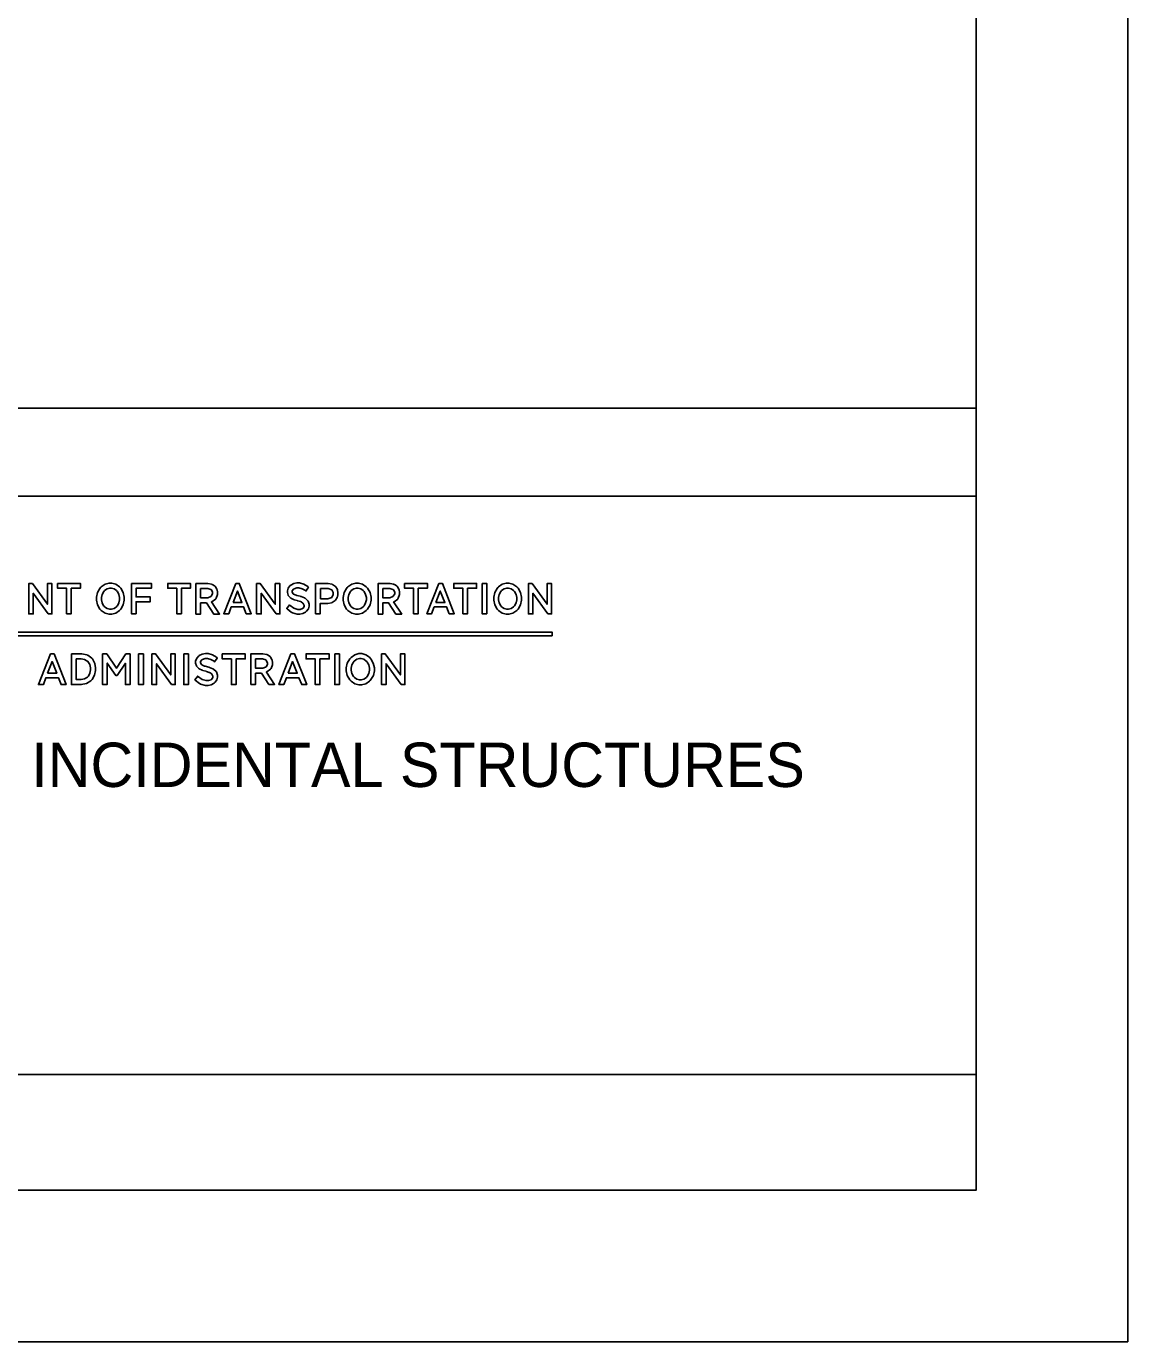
# Model space of a CAD drawing. Extents: x -0.5 to 19.9, y 5.2 to 17.3.
# Drawn here: x 17.634 to 19.938, y 5.667 to 8.417 of the extents above; entities that cross this region are included whole.
import ezdxf

# ---------------------------------------------------------------- set-up
doc = ezdxf.new("R2010")
doc.units = 0
for name, color, linetype in [('BORD-LINE', 7, 'Continuous'), ('MSHA-LOGO', 7, 'Continuous'), ('TTLB-TEXT', 7, 'Continuous'), ('USER-CLIP', 7, 'Continuous')]:
    doc.layers.add(name, color=color, linetype=linetype)

msp = doc.modelspace()

# ---------------------------------------------------------------- linework, layer by layer
at = {"layer": 'BORD-LINE'}
for p, q in [((19.6208, 7.6193), (12.2466, 7.6193)), ((19.6208, 7.4352), (15.1479, 7.4352)), ((15.1479, 6.2262), (19.6208, 6.2262))]:
    msp.add_line(p, q, dxfattribs=at)
msp.add_lwpolyline([(12.2466, 16.3375), (19.6208, 16.3375), (19.6208, 5.9844), (12.2466, 5.9844)], close=True, dxfattribs=at)
at = {"layer": 'MSHA-LOGO'}
for points in [[(17.6799, 7.189), (17.6485, 7.2324), (17.6485, 7.189), (17.639, 7.189), (17.639, 7.2525), (17.6465, 7.2525), (17.6779, 7.2091), (17.6779, 7.2525), (17.6874, 7.2525), (17.6874, 7.189)], [(17.6989, 7.2528), (17.747, 7.2528), (17.747, 7.2426), (17.728, 7.2426), (17.728, 7.1893), (17.7182, 7.1893), (17.7182, 7.2426), (17.6992, 7.2426), (17.6992, 7.2528)], [(17.7892, 7.2439), (17.7905, 7.2455), (17.7985, 7.251), (17.8069, 7.2535), (17.8098, 7.2535), (17.8126, 7.2535), (17.821, 7.2512), (17.829, 7.2458), (17.8304, 7.2443), (17.8318, 7.2427), (17.8367, 7.2338), (17.8389, 7.2241), (17.8389, 7.2209), (17.8389, 7.2177), (17.8367, 7.2081), (17.8318, 7.1991), (17.8304, 7.1975), (17.829, 7.196), (17.821, 7.1906), (17.8126, 7.1883), (17.8098, 7.1883), (17.8069, 7.1883), (17.7985, 7.1906), (17.7905, 7.196), (17.7892, 7.1975), (17.7878, 7.1991), (17.7828, 7.208), (17.7807, 7.2177), (17.7807, 7.2209), (17.7807, 7.2241), (17.7828, 7.2335), (17.7878, 7.2424)], [(17.7967, 7.2051), (17.7976, 7.204), (17.8028, 7.2004), (17.8083, 7.1989), (17.8101, 7.1989), (17.8119, 7.1989), (17.8174, 7.2004), (17.8226, 7.204), (17.8235, 7.2051), (17.8244, 7.2061), (17.8276, 7.212), (17.8291, 7.2187), (17.8291, 7.2209), (17.8291, 7.2231), (17.8276, 7.2298), (17.8244, 7.2357), (17.8235, 7.2367), (17.8226, 7.2378), (17.8174, 7.2414), (17.8119, 7.2429), (17.8101, 7.2429), (17.8083, 7.2429), (17.8028, 7.2414), (17.7976, 7.2378), (17.7967, 7.2367), (17.7958, 7.2357), (17.7925, 7.2298), (17.7911, 7.2231), (17.7911, 7.2209), (17.7911, 7.2187), (17.7924, 7.212), (17.7957, 7.2061)], [(17.8536, 7.2528), (17.8955, 7.2528), (17.8955, 7.2426), (17.8634, 7.2426), (17.8634, 7.2245), (17.8932, 7.2245), (17.8932, 7.2143), (17.8634, 7.2143), (17.8634, 7.1893), (17.8536, 7.1893)], [(17.9292, 7.2528), (17.9773, 7.2528), (17.9773, 7.2426), (17.9583, 7.2426), (17.9583, 7.1893), (17.9485, 7.1893), (17.9485, 7.2426), (17.9296, 7.2426), (17.9296, 7.2528)], [(17.9888, 7.189), (17.9888, 7.2525), (18.011, 7.2525), (18.0138, 7.2525), (18.0213, 7.2511), (18.0222, 7.2508), (18.0229, 7.2506), (18.0286, 7.2467), (18.029, 7.2462), (18.0294, 7.2458), (18.0324, 7.2406), (18.0326, 7.24), (18.0329, 7.2394), (18.0336, 7.2342), (18.0336, 7.2324), (18.0336, 7.2295), (18.0309, 7.2217), (18.0303, 7.2209), (18.0298, 7.2201), (18.0222, 7.2143), (18.0212, 7.214), (18.0382, 7.1887), (18.0261, 7.1887), (18.0107, 7.212), (17.9986, 7.212), (17.9986, 7.1887), (17.9888, 7.1887)], [(17.9986, 7.2423), (17.9986, 7.2229), (18.0114, 7.2229), (18.0136, 7.2229), (18.0196, 7.2251), (18.0202, 7.2255), (18.0207, 7.2259), (18.0235, 7.2313), (18.0235, 7.2331), (18.0235, 7.2348), (18.021, 7.2396), (18.0205, 7.24), (18.02, 7.2404), (18.0133, 7.2423), (18.011, 7.2423)], [(18.0719, 7.2528), (18.0794, 7.2528), (18.1043, 7.1893), (18.0938, 7.1893), (18.0883, 7.2035), (18.0627, 7.2035), (18.0572, 7.1893), (18.047, 7.1893)], [(18.0663, 7.2127), (18.085, 7.2127), (18.0755, 7.2367)], [(18.1566, 7.189), (18.1252, 7.2324), (18.1252, 7.189), (18.1157, 7.189), (18.1157, 7.2525), (18.1233, 7.2525), (18.1547, 7.2091), (18.1547, 7.2525), (18.1642, 7.2525), (18.1642, 7.189)], [(18.213, 7.2114), (18.2126, 7.2117), (18.2085, 7.2144), (18.208, 7.2147), (18.2075, 7.2148), (18.2018, 7.2165), (18.2012, 7.2166), (18.2005, 7.2168), (18.1943, 7.2187), (18.1936, 7.2189), (18.193, 7.2192), (18.1872, 7.2219), (18.1868, 7.2222), (18.1863, 7.2226), (18.1822, 7.2269), (18.1819, 7.2275), (18.1815, 7.2281), (18.1799, 7.2338), (18.1799, 7.2357), (18.1799, 7.2374), (18.1814, 7.2426), (18.185, 7.2476), (18.1861, 7.2485), (18.1872, 7.2494), (18.1933, 7.2525), (18.1999, 7.2538), (18.2021, 7.2538), (18.2053, 7.2538), (18.2147, 7.2515), (18.2228, 7.2462), (18.2241, 7.2446), (18.2188, 7.2367), (18.2176, 7.2378), (18.2109, 7.2416), (18.2041, 7.2433), (18.2018, 7.2433), (18.1997, 7.2433), (18.1939, 7.2416), (18.1933, 7.2413), (18.1927, 7.241), (18.19, 7.237), (18.19, 7.2357), (18.19, 7.2345), (18.1922, 7.2311), (18.1926, 7.2308), (18.1931, 7.2305), (18.1985, 7.228), (18.1992, 7.2278), (18.1998, 7.2277), (18.207, 7.2258), (18.2077, 7.2255), (18.2085, 7.2253), (18.2156, 7.2226), (18.2162, 7.2222), (18.2169, 7.2219), (18.2224, 7.2173), (18.2228, 7.2166), (18.2232, 7.216), (18.2254, 7.2095), (18.2254, 7.2074), (18.2254, 7.2055), (18.2239, 7.1999), (18.2202, 7.1948), (18.2192, 7.1939), (18.2181, 7.193), (18.2121, 7.1899), (18.2058, 7.1887), (18.2038, 7.1887), (18.2002, 7.1887), (18.1905, 7.1914), (18.1894, 7.192), (18.1882, 7.1925), (18.1792, 7.1994), (18.1786, 7.2002), (18.1845, 7.2077), (18.1858, 7.2063), (18.1934, 7.2009), (18.2017, 7.1985), (18.2044, 7.1985), (18.2064, 7.1985), (18.2119, 7.2002), (18.2123, 7.2005), (18.2128, 7.2008), (18.2152, 7.2048), (18.2152, 7.2061), (18.2151, 7.2067), (18.2133, 7.211)], [(18.2391, 7.189), (18.2391, 7.2525), (18.262, 7.2525), (18.265, 7.2525), (18.273, 7.2511), (18.2738, 7.2508), (18.2746, 7.2505), (18.2806, 7.2464), (18.281, 7.2459), (18.2814, 7.2454), (18.2845, 7.2399), (18.2846, 7.2393), (18.2848, 7.2388), (18.2856, 7.2335), (18.2856, 7.2318), (18.2856, 7.2299), (18.2845, 7.2248), (18.2843, 7.2242), (18.284, 7.2236), (18.2808, 7.2181), (18.2804, 7.2176), (18.2799, 7.2171), (18.2736, 7.213), (18.2728, 7.2127), (18.272, 7.2124), (18.2643, 7.211), (18.2617, 7.211), (18.2486, 7.211), (18.2486, 7.1893), (18.2391, 7.1893)], [(18.2493, 7.2423), (18.2493, 7.2209), (18.2624, 7.2209), (18.2649, 7.2209), (18.2727, 7.2236), (18.2761, 7.2297), (18.2761, 7.2318), (18.2761, 7.2337), (18.2729, 7.2396), (18.2655, 7.2423), (18.263, 7.2423)], [(18.3052, 7.2439), (18.3066, 7.2455), (18.3146, 7.251), (18.323, 7.2535), (18.3259, 7.2535), (18.3287, 7.2535), (18.3371, 7.2512), (18.3451, 7.2458), (18.3465, 7.2443), (18.3478, 7.2427), (18.3528, 7.2338), (18.355, 7.2241), (18.355, 7.2209), (18.355, 7.2177), (18.3528, 7.2081), (18.3478, 7.1991), (18.3465, 7.1975), (18.3451, 7.196), (18.3371, 7.1906), (18.3287, 7.1883), (18.3259, 7.1883), (18.323, 7.1883), (18.3146, 7.1906), (18.3066, 7.196), (18.3052, 7.1975), (18.3038, 7.1991), (18.2989, 7.208), (18.2967, 7.2177), (18.2967, 7.2209), (18.2968, 7.2232), (18.299, 7.2335), (18.3038, 7.2424)], [(18.3128, 7.2051), (18.3136, 7.204), (18.3188, 7.2004), (18.3243, 7.1989), (18.3262, 7.1989), (18.328, 7.1989), (18.3335, 7.2004), (18.3387, 7.204), (18.3396, 7.2051), (18.3405, 7.2061), (18.3437, 7.212), (18.3452, 7.2187), (18.3452, 7.2209), (18.3452, 7.2231), (18.3437, 7.2298), (18.3405, 7.2357), (18.3396, 7.2367), (18.3387, 7.2378), (18.3335, 7.2414), (18.328, 7.2429), (18.3262, 7.2429), (18.3244, 7.2429), (18.319, 7.2414), (18.3137, 7.2378), (18.3128, 7.2367), (18.3119, 7.2357), (18.3086, 7.2298), (18.3072, 7.2231), (18.3072, 7.2209), (18.3072, 7.2187), (18.3085, 7.212), (18.3118, 7.2061)], [(18.3697, 7.189), (18.3697, 7.2525), (18.3919, 7.2525), (18.3947, 7.2525), (18.4023, 7.2511), (18.4031, 7.2508), (18.4038, 7.2506), (18.4095, 7.2467), (18.4099, 7.2462), (18.4104, 7.2458), (18.4133, 7.2406), (18.4135, 7.24), (18.4137, 7.2394), (18.4145, 7.2342), (18.4145, 7.2324), (18.4145, 7.2295), (18.4118, 7.2217), (18.4113, 7.2209), (18.4107, 7.2201), (18.4031, 7.2143), (18.4021, 7.214), (18.4191, 7.1887), (18.407, 7.1887), (18.3916, 7.212), (18.3795, 7.212), (18.3795, 7.1887), (18.3697, 7.1887)], [(18.3795, 7.2423), (18.3795, 7.2229), (18.3923, 7.2229), (18.3945, 7.2229), (18.4005, 7.2251), (18.4011, 7.2255), (18.4016, 7.2259), (18.4044, 7.2313), (18.4044, 7.2331), (18.4044, 7.2348), (18.4019, 7.2396), (18.4014, 7.24), (18.4009, 7.2404), (18.3942, 7.2423), (18.3919, 7.2423)], [(18.4247, 7.2528), (18.4728, 7.2528), (18.4728, 7.2426), (18.4538, 7.2426), (18.4538, 7.1893), (18.444, 7.1893), (18.444, 7.2426), (18.425, 7.2426), (18.425, 7.2528)], [(18.4967, 7.2528), (18.5042, 7.2528), (18.5291, 7.1893), (18.5186, 7.1893), (18.513, 7.2035), (18.4872, 7.2035), (18.4816, 7.1893), (18.4718, 7.1893)], [(18.4908, 7.2127), (18.5094, 7.2127), (18.4999, 7.2367)], [(18.5278, 7.2528), (18.5759, 7.2528), (18.5759, 7.2426), (18.5569, 7.2426), (18.5569, 7.1893), (18.5471, 7.1893), (18.5471, 7.2426), (18.5281, 7.2426), (18.5281, 7.2528)], [(18.5873, 7.2528), (18.5971, 7.2528), (18.5971, 7.1893), (18.5873, 7.1893)], [(18.6201, 7.2439), (18.6214, 7.2455), (18.6294, 7.251), (18.6378, 7.2535), (18.6407, 7.2535), (18.6435, 7.2535), (18.6519, 7.2512), (18.6599, 7.2458), (18.6613, 7.2443), (18.6627, 7.2427), (18.6676, 7.2338), (18.6698, 7.2241), (18.6698, 7.2209), (18.6698, 7.2177), (18.6676, 7.2081), (18.6627, 7.1991), (18.6613, 7.1975), (18.6599, 7.196), (18.6519, 7.1906), (18.6435, 7.1883), (18.6407, 7.1883), (18.6378, 7.1883), (18.6294, 7.1906), (18.6214, 7.196), (18.6201, 7.1975), (18.6187, 7.1991), (18.6137, 7.208), (18.6115, 7.2177), (18.6115, 7.2209), (18.6115, 7.2241), (18.6136, 7.2335), (18.6186, 7.2424)], [(18.6272, 7.2051), (18.6281, 7.204), (18.6333, 7.2004), (18.6388, 7.1989), (18.6407, 7.1989), (18.6425, 7.1989), (18.648, 7.2004), (18.6532, 7.204), (18.6541, 7.2051), (18.655, 7.2061), (18.6582, 7.212), (18.6596, 7.2187), (18.6596, 7.2209), (18.6596, 7.2231), (18.6582, 7.2298), (18.655, 7.2357), (18.6541, 7.2367), (18.6532, 7.2378), (18.648, 7.2414), (18.6425, 7.2429), (18.6407, 7.2429), (18.6389, 7.2429), (18.6335, 7.2414), (18.6282, 7.2378), (18.6272, 7.2367), (18.6263, 7.2357), (18.6231, 7.2298), (18.6217, 7.2231), (18.6217, 7.2209), (18.6217, 7.2187), (18.6231, 7.212), (18.6263, 7.2061)], [(18.7251, 7.189), (18.6937, 7.2324), (18.6937, 7.189), (18.6842, 7.189), (18.6842, 7.2525), (18.6917, 7.2525), (18.7231, 7.2091), (18.7231, 7.2525), (18.7326, 7.2525), (18.7326, 7.189)], [(16.617, 7.151), (18.7337, 7.151), (18.7337, 7.1432), (16.617, 7.1432)], [(17.6843, 7.1055), (17.6919, 7.1055), (17.7172, 7.0413), (17.7066, 7.0413), (17.7012, 7.0554), (17.675, 7.0554), (17.6696, 7.0413), (17.6593, 7.0413)], [(17.7284, 7.1055), (17.7462, 7.1055), (17.75, 7.1055), (17.7602, 7.1033), (17.7613, 7.1029), (17.7623, 7.1025), (17.7708, 7.0967), (17.7715, 7.0959), (17.7721, 7.0951), (17.7766, 7.0869), (17.7769, 7.0859), (17.7772, 7.085), (17.7785, 7.0768), (17.7785, 7.074), (17.7785, 7.0707), (17.7764, 7.0608), (17.7716, 7.0518), (17.7702, 7.0503), (17.7688, 7.0488), (17.7598, 7.0435), (17.7489, 7.0413), (17.7453, 7.0413), (17.7284, 7.0413)], [(17.7932, 7.1055), (17.8022, 7.1055), (17.8226, 7.0756), (17.8424, 7.1055), (17.8511, 7.1055), (17.8511, 7.0413), (17.8411, 7.0413), (17.8411, 7.0859), (17.8236, 7.0605), (17.821, 7.0605), (17.8031, 7.0862), (17.8031, 7.0416), (17.7932, 7.0416)], [(17.8689, 7.1055), (17.8788, 7.1055), (17.8788, 7.0413), (17.8689, 7.0413)], [(17.9379, 7.0413), (17.9063, 7.085), (17.9063, 7.0413), (17.8967, 7.0413), (17.8967, 7.1055), (17.9044, 7.1055), (17.936, 7.0615), (17.936, 7.1055), (17.9456, 7.1055), (17.9456, 7.0413)], [(17.9632, 7.1055), (17.9731, 7.1055), (17.9731, 7.0413), (17.9632, 7.0413)], [(18.022, 7.0634), (18.0217, 7.0638), (18.0174, 7.0664), (18.0169, 7.0667), (18.0163, 7.0668), (18.0105, 7.0688), (18.0098, 7.0689), (18.0092, 7.0691), (18.0028, 7.0709), (18.0022, 7.0711), (18.0015, 7.0714), (17.9957, 7.074), (17.9951, 7.0744), (17.9946, 7.0747), (17.9904, 7.0793), (17.99, 7.0798), (17.9897, 7.0804), (17.9881, 7.0862), (17.9881, 7.0882), (17.9881, 7.0899), (17.9898, 7.0952), (17.9935, 7.1001), (17.9945, 7.101), (17.9955, 7.1019), (18.0017, 7.1049), (18.0085, 7.1062), (18.0108, 7.1062), (18.014, 7.1062), (18.0235, 7.1038), (18.0318, 7.0984), (18.0332, 7.0968), (18.0277, 7.0888), (18.0265, 7.0899), (18.0198, 7.0939), (18.0128, 7.0956), (18.0105, 7.0956), (18.0083, 7.0956), (18.0024, 7.094), (18.0019, 7.0936), (18.0013, 7.0933), (17.9983, 7.0892), (17.9983, 7.0878), (17.9983, 7.0866), (18.0005, 7.0831), (18.0009, 7.0827), (18.0013, 7.0824), (18.0069, 7.08), (18.0076, 7.0798), (18.0083, 7.0797), (18.0154, 7.0775), (18.0162, 7.0773), (18.017, 7.077), (18.0242, 7.0743), (18.0249, 7.074), (18.0255, 7.0737), (18.0311, 7.0689), (18.0316, 7.0683), (18.032, 7.0676), (18.0341, 7.0611), (18.0341, 7.0589), (18.0341, 7.0571), (18.0325, 7.0513), (18.0288, 7.046), (18.0277, 7.0451), (18.0267, 7.0443), (18.0206, 7.0411), (18.0142, 7.0397), (18.0121, 7.0397), (18.0084, 7.0397), (17.9986, 7.0423), (17.9974, 7.0429), (17.9962, 7.0435), (17.9872, 7.0504), (17.9865, 7.0512), (17.9926, 7.0589), (17.9939, 7.0574), (18.0015, 7.052), (18.0101, 7.0496), (18.013, 7.0496), (18.015, 7.0496), (18.0205, 7.0512), (18.021, 7.0516), (18.0215, 7.0519), (18.0239, 7.056), (18.0239, 7.0573), (18.0239, 7.0589), (18.0223, 7.0631)], [(18.0434, 7.1055), (18.092, 7.1055), (18.092, 7.0949), (18.0728, 7.0949), (18.0728, 7.0413), (18.0629, 7.0413), (18.0629, 7.0949), (18.0437, 7.0949), (18.0437, 7.1055)], [(18.1035, 7.0413), (18.1035, 7.1055), (18.1261, 7.1055), (18.1289, 7.1055), (18.1365, 7.1041), (18.1373, 7.1039), (18.1381, 7.1037), (18.144, 7.0999), (18.1444, 7.0994), (18.1448, 7.0989), (18.1477, 7.0936), (18.1479, 7.093), (18.148, 7.0924), (18.1488, 7.0873), (18.1488, 7.0856), (18.1488, 7.0827), (18.1459, 7.0748), (18.1453, 7.074), (18.1447, 7.0732), (18.137, 7.0676), (18.136, 7.0673), (18.1533, 7.0416), (18.1412, 7.0416), (18.1255, 7.065), (18.1134, 7.065), (18.1134, 7.0416), (18.1035, 7.0416)], [(18.1875, 7.1055), (18.1952, 7.1055), (18.2204, 7.0413), (18.2099, 7.0413), (18.2041, 7.0554), (18.1779, 7.0554), (18.1725, 7.0413), (18.1623, 7.0413)], [(18.2188, 7.1055), (18.2674, 7.1055), (18.2674, 7.0949), (18.2482, 7.0949), (18.2482, 7.0413), (18.2383, 7.0413), (18.2383, 7.0949), (18.2191, 7.0949), (18.2191, 7.1055)], [(18.2789, 7.1055), (18.2888, 7.1055), (18.2888, 7.0413), (18.2789, 7.0413)], [(18.3118, 7.0965), (18.3132, 7.0981), (18.3213, 7.1037), (18.3297, 7.1062), (18.3325, 7.1062), (18.3354, 7.1062), (18.3439, 7.1038), (18.3519, 7.0984), (18.3533, 7.0968), (18.3547, 7.0953), (18.3597, 7.0863), (18.362, 7.0766), (18.362, 7.0734), (18.362, 7.0702), (18.3598, 7.0606), (18.3547, 7.0516), (18.3533, 7.05), (18.3519, 7.0484), (18.3438, 7.0429), (18.3353, 7.0406), (18.3325, 7.0406), (18.3297, 7.0406), (18.3211, 7.043), (18.3131, 7.0484), (18.3118, 7.05), (18.3103, 7.0515), (18.3053, 7.0605), (18.3032, 7.0702), (18.3032, 7.0734), (18.3032, 7.0766), (18.3053, 7.0861), (18.3103, 7.095)], [(18.3191, 7.0573), (18.3201, 7.0563), (18.3254, 7.0527), (18.3308, 7.0512), (18.3325, 7.0512), (18.3344, 7.0512), (18.34, 7.0527), (18.3453, 7.0563), (18.3463, 7.0573), (18.3472, 7.0584), (18.3504, 7.0644), (18.3517, 7.0711), (18.3517, 7.0734), (18.3517, 7.0756), (18.3503, 7.0823), (18.3469, 7.0884), (18.346, 7.0894), (18.345, 7.0905), (18.3397, 7.0941), (18.3343, 7.0956), (18.3325, 7.0956), (18.3307, 7.0956), (18.3252, 7.0941), (18.32, 7.0905), (18.3191, 7.0894), (18.3183, 7.0884), (18.3151, 7.0824), (18.3137, 7.0756), (18.3137, 7.0734), (18.3137, 7.0711), (18.3151, 7.0644), (18.3183, 7.0584)], [(18.4182, 7.0413), (18.3865, 7.085), (18.3865, 7.0413), (18.377, 7.0413), (18.377, 7.1055), (18.3846, 7.1055), (18.4163, 7.0615), (18.4163, 7.1055), (18.4259, 7.1055), (18.4259, 7.0413)], [(17.6785, 7.065), (17.6974, 7.065), (17.6878, 7.0894)], [(17.7383, 7.0949), (17.7383, 7.0516), (17.7459, 7.0516), (17.7484, 7.0516), (17.7558, 7.0531), (17.7619, 7.0566), (17.7629, 7.0577), (17.7638, 7.0587), (17.767, 7.0649), (17.7683, 7.0718), (17.7683, 7.074), (17.7683, 7.0763), (17.7669, 7.0831), (17.7628, 7.0897), (17.7559, 7.0936), (17.7486, 7.0949), (17.7462, 7.0949)], [(18.1134, 7.0949), (18.1134, 7.0753), (18.1261, 7.0753), (18.1284, 7.0753), (18.1345, 7.0775), (18.1351, 7.0779), (18.1356, 7.0784), (18.1383, 7.0836), (18.1383, 7.0853), (18.1383, 7.0871), (18.1359, 7.0919), (18.1354, 7.0923), (18.1349, 7.0927), (18.1281, 7.0949), (18.1258, 7.0949)], [(18.1817, 7.065), (18.2006, 7.065), (18.191, 7.0894)]]:
    msp.add_lwpolyline(points, close=True, dxfattribs=at)
at = {"layer": 'USER-CLIP'}
msp.add_lwpolyline([(19.9377, 16.6675), (11.4377, 16.6675), (11.4377, 5.6675), (19.9377, 5.6675)], close=True, dxfattribs=at)

# ---------------------------------------------------------------- texts
at = {"layer": 'BORD-LINE'}
msp.add_text('HDVBARREIRA', height=6e-12, rotation=180, dxfattribs=at).set_placement((19.6208, 7.4352))
at = {"layer": 'TTLB-TEXT'}
msp.add_text('STANDARDS FOR HIGHWAYS AND INCIDENTAL STRUCTURES', height=0.09269, dxfattribs=at).set_placement((15.5437, 6.8272))

doc.saveas('drawing.dxf')
